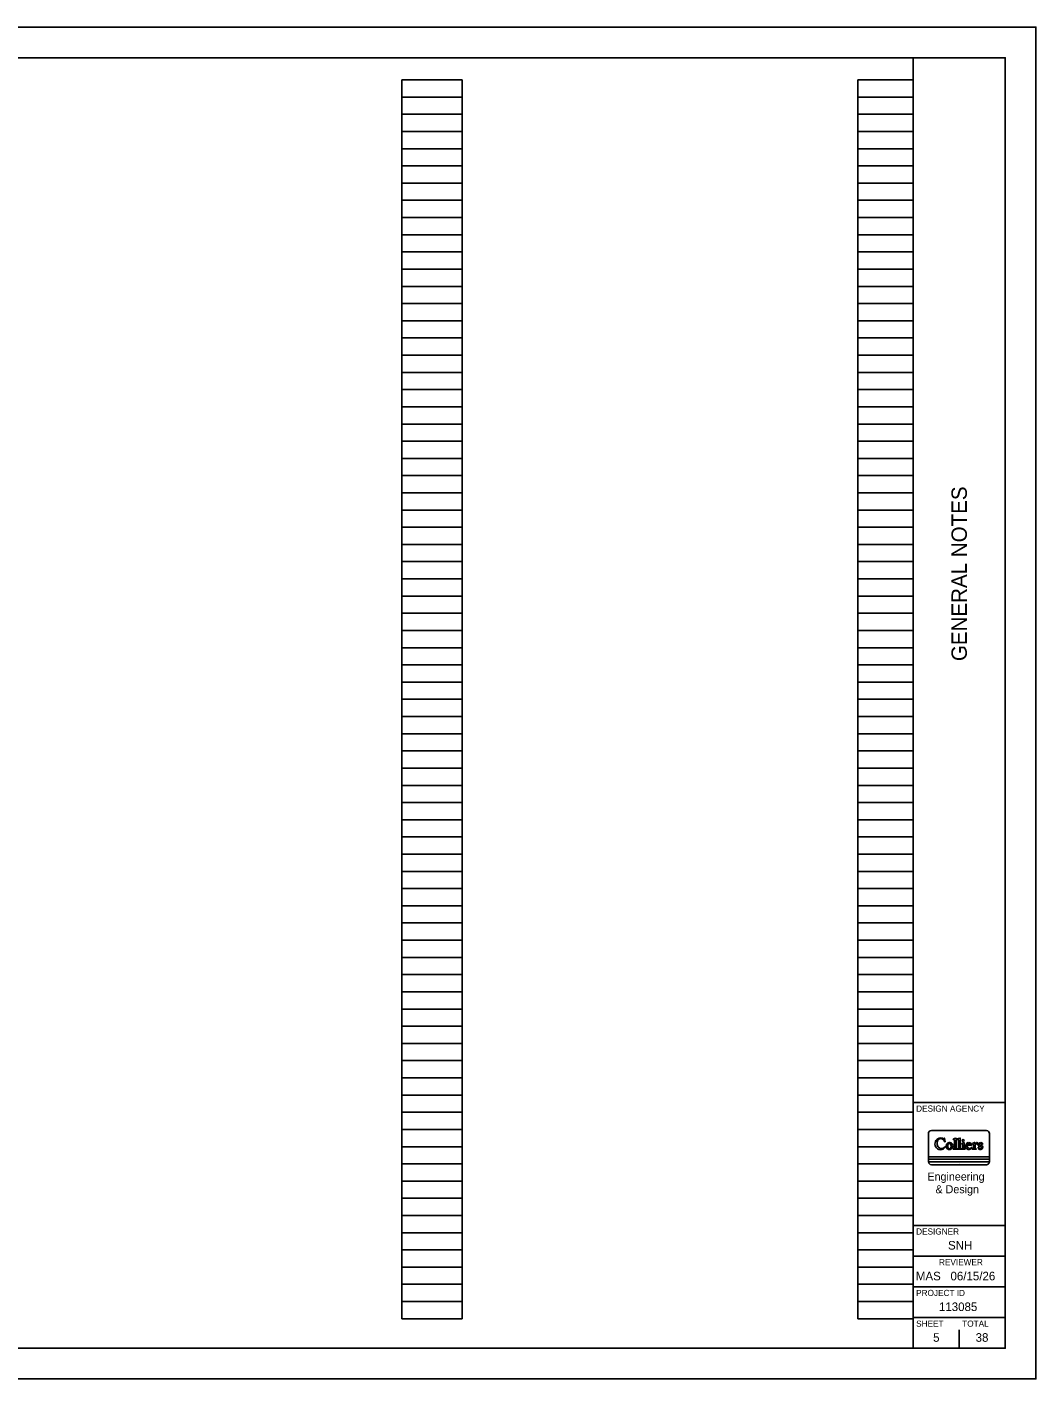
# Model space of a CAD drawing. Extents: x 0 to 34, y 0 to 22.
# Drawn here: x 17.58 to 34, y 0 to 22 of the extents above; entities that cross this region are included whole.
import ezdxf

# ---------------------------------------------------------------- set-up
doc = ezdxf.new("R2010")
doc.units = 0
for name, color, linetype in [('SH_Border', 7, 'Continuous'), ('SH_Cut_Line', 7, 'Continuous'), ('SH_Data', 7, 'Continuous')]:
    doc.layers.add(name, color=color, linetype=linetype)

msp = doc.modelspace()

# ---------------------------------------------------------------- linework, layer by layer
at = {"layer": 'SH_Border'}
for p, q in [((32, 0.5), (32, 21.5)), ((32, 4.5), (33.5, 4.5)), ((32, 2.5), (33.5, 2.5)), ((32, 2), (33.5, 2)), ((32, 1.5), (33.5, 1.5)), ((32, 1), (33.5, 1))]:
    msp.add_line(p, q, dxfattribs=at)
msp.add_lwpolyline([(1.5, 21.5), (33.5, 21.5), (33.5, 0.5), (1.5, 0.5)], close=True, dxfattribs=at)
at = {"layer": 'SH_Cut_Line'}
msp.add_lwpolyline([(0, 0), (34, 0), (34, 22), (0, 22)], close=True, dxfattribs=at)
at = {"layer": 'SH_Data'}
for p, q in [((23.68, 0.98), (23.68, 21.14)), ((23.68, 21.14), (24.66, 21.14)), ((24.66, 0.98), (24.66, 21.14)), ((31.1, 0.98), (31.1, 21.14)), ((31.1, 21.14), (32, 21.14)), ((32, 0.98), (32, 21.14)), ((23.68, 20.86), (24.66, 20.86)), ((31.1, 20.86), (32, 20.86)), ((23.68, 20.58), (24.66, 20.58)), ((31.1, 20.58), (32, 20.58)), ((23.68, 20.3), (24.66, 20.3)), ((31.1, 20.3), (32, 20.3)), ((23.68, 20.02), (24.66, 20.02)), ((31.1, 20.02), (32, 20.02)), ((23.68, 19.74), (24.66, 19.74)), ((31.1, 19.74), (32, 19.74)), ((23.68, 19.46), (24.66, 19.46)), ((31.1, 19.46), (32, 19.46)), ((23.68, 19.18), (24.66, 19.18)), ((31.1, 19.18), (32, 19.18)), ((23.68, 18.9), (24.66, 18.9)), ((31.1, 18.9), (32, 18.9)), ((23.68, 18.62), (24.66, 18.62)), ((31.1, 18.62), (32, 18.62)), ((23.68, 18.34), (24.66, 18.34)), ((31.1, 18.34), (32, 18.34)), ((23.68, 18.06), (24.66, 18.06)), ((31.1, 18.06), (32, 18.06)), ((23.68, 17.78), (24.66, 17.78)), ((31.1, 17.78), (32, 17.78)), ((23.68, 17.5), (24.66, 17.5)), ((31.1, 17.5), (32, 17.5)), ((23.68, 17.22), (24.66, 17.22)), ((31.1, 17.22), (32, 17.22)), ((23.68, 16.94), (24.66, 16.94)), ((31.1, 16.94), (32, 16.94)), ((23.68, 16.66), (24.66, 16.66)), ((31.1, 16.66), (32, 16.66)), ((23.68, 16.38), (24.66, 16.38)), ((31.1, 16.38), (32, 16.38)), ((23.68, 16.1), (24.66, 16.1)), ((31.1, 16.1), (32, 16.1)), ((23.68, 15.82), (24.66, 15.82)), ((31.1, 15.82), (32, 15.82)), ((23.68, 15.54), (24.66, 15.54)), ((31.1, 15.54), (32, 15.54)), ((23.68, 15.26), (24.66, 15.26)), ((31.1, 15.26), (32, 15.26)), ((23.68, 14.98), (24.66, 14.98)), ((31.1, 14.98), (32, 14.98)), ((23.68, 14.7), (24.66, 14.7)), ((31.1, 14.7), (32, 14.7)), ((23.68, 14.42), (24.66, 14.42)), ((31.1, 14.42), (32, 14.42)), ((23.68, 14.14), (24.66, 14.14)), ((31.1, 14.14), (32, 14.14)), ((23.68, 13.86), (24.66, 13.86)), ((31.1, 13.86), (32, 13.86)), ((23.68, 13.58), (24.66, 13.58)), ((31.1, 13.58), (32, 13.58)), ((23.68, 13.3), (24.66, 13.3)), ((31.1, 13.3), (32, 13.3)), ((23.68, 13.02), (24.66, 13.02)), ((31.1, 13.02), (32, 13.02)), ((23.68, 12.74), (24.66, 12.74)), ((31.1, 12.74), (32, 12.74)), ((23.68, 12.46), (24.66, 12.46)), ((31.1, 12.46), (32, 12.46)), ((23.68, 12.18), (24.66, 12.18)), ((31.1, 12.18), (32, 12.18)), ((23.68, 11.9), (24.66, 11.9)), ((31.1, 11.9), (32, 11.9)), ((23.68, 11.62), (24.66, 11.62)), ((31.1, 11.62), (32, 11.62)), ((23.68, 11.34), (24.66, 11.34)), ((31.1, 11.34), (32, 11.34)), ((23.68, 11.06), (24.66, 11.06)), ((31.1, 11.06), (32, 11.06)), ((23.68, 10.78), (24.66, 10.78)), ((31.1, 10.78), (32, 10.78)), ((23.68, 10.5), (24.66, 10.5)), ((31.1, 10.5), (32, 10.5)), ((23.68, 10.22), (24.66, 10.22)), ((31.1, 10.22), (32, 10.22)), ((23.68, 9.94), (24.66, 9.94)), ((31.1, 9.94), (32, 9.94)), ((23.68, 9.66), (24.66, 9.66)), ((31.1, 9.66), (32, 9.66)), ((23.68, 9.38), (24.66, 9.38)), ((31.1, 9.38), (32, 9.38)), ((23.68, 9.1), (24.66, 9.1)), ((31.1, 9.1), (32, 9.1)), ((23.68, 8.82), (24.66, 8.82)), ((31.1, 8.82), (32, 8.82)), ((23.68, 8.54), (24.66, 8.54)), ((31.1, 8.54), (32, 8.54)), ((23.68, 8.26), (24.66, 8.26)), ((31.1, 8.26), (32, 8.26)), ((23.68, 7.98), (24.66, 7.98)), ((31.1, 7.98), (32, 7.98)), ((23.68, 7.7), (24.66, 7.7)), ((31.1, 7.7), (32, 7.7)), ((23.68, 7.42), (24.66, 7.42)), ((31.1, 7.42), (32, 7.42)), ((23.68, 7.14), (24.66, 7.14)), ((31.1, 7.14), (32, 7.14)), ((23.68, 6.86), (24.66, 6.86)), ((31.1, 6.86), (32, 6.86)), ((23.68, 6.58), (24.66, 6.58)), ((31.1, 6.58), (32, 6.58)), ((23.68, 6.3), (24.66, 6.3)), ((31.1, 6.3), (32, 6.3)), ((23.68, 6.02), (24.66, 6.02)), ((31.1, 6.02), (32, 6.02)), ((23.68, 5.74), (24.66, 5.74)), ((31.1, 5.74), (32, 5.74)), ((23.68, 5.46), (24.66, 5.46)), ((31.1, 5.46), (32, 5.46)), ((23.68, 5.18), (24.66, 5.18)), ((31.1, 5.18), (32, 5.18)), ((23.68, 4.9), (24.66, 4.9)), ((31.1, 4.9), (32, 4.9)), ((23.68, 4.62), (24.66, 4.62)), ((31.1, 4.62), (32, 4.62)), ((23.68, 4.34), (24.66, 4.34)), ((31.1, 4.34), (32, 4.34)), ((23.68, 4.06), (24.66, 4.06)), ((31.1, 4.06), (32, 4.06)), ((33.195, 4.043), (32.299, 4.043)), ((23.68, 3.78), (24.66, 3.78)), ((31.1, 3.78), (32, 3.78)), ((32.506, 3.913), (32.507, 3.91)), ((32.511, 3.864), (32.513, 3.859)), ((32.518, 3.765), (32.522, 3.77)), ((32.596, 3.846), (32.59, 3.846)), ((32.667, 3.745), (32.658, 3.745)), ((32.674, 3.881), (32.674, 3.753)), ((32.701, 3.752), (32.701, 3.916)), ((32.734, 3.745), (32.707, 3.745)), ((32.741, 3.879), (32.741, 3.751)), ((32.768, 3.751), (32.768, 3.916)), ((32.799, 3.745), (32.774, 3.745)), ((32.827, 3.846), (32.791, 3.832)), ((32.805, 3.812), (32.805, 3.751)), ((32.832, 3.749), (32.832, 3.843)), ((32.845, 3.745), (32.836, 3.745)), ((32.886, 3.802), (32.947, 3.802)), ((32.919, 3.81), (32.887, 3.81)), ((32.975, 3.745), (32.968, 3.745)), ((33, 3.846), (32.969, 3.831)), ((32.969, 3.825), (32.976, 3.821)), ((32.982, 3.81), (32.982, 3.753)), ((33.007, 3.828), (33.006, 3.843)), ((33.01, 3.753), (33.01, 3.807)), ((33.026, 3.745), (33.017, 3.745)), ((33.11, 3.833), (33.125, 3.816)), ((33.132, 3.82), (33.13, 3.835)), ((32.249, 3.533), (33.244, 3.533)), ((33.244, 3.533), (32.249, 3.533)), ((32.658, 3.737), (32.845, 3.737)), ((32.968, 3.737), (33.026, 3.737)), ((33.245, 3.535), (33.245, 3.575)), ((23.68, 3.5), (24.66, 3.5)), ((31.1, 3.5), (32, 3.5)), ((32.299, 3.485), (33.195, 3.485)), ((32.75, 3.5), (32.75, 3.5)), ((23.68, 3.22), (24.66, 3.22)), ((31.1, 3.22), (32, 3.22)), ((23.68, 2.94), (24.66, 2.94)), ((31.1, 2.94), (32, 2.94)), ((23.68, 2.66), (24.66, 2.66)), ((31.1, 2.66), (32, 2.66)), ((23.68, 2.38), (24.66, 2.38)), ((31.1, 2.38), (32, 2.38)), ((23.68, 2.1), (24.66, 2.1)), ((31.1, 2.1), (32, 2.1)), ((23.68, 1.82), (24.66, 1.82)), ((31.1, 1.82), (32, 1.82)), ((23.68, 1.54), (24.66, 1.54)), ((31.1, 1.54), (32, 1.54)), ((23.68, 1.26), (24.66, 1.26)), ((31.1, 1.26), (32, 1.26)), ((23.68, 0.98), (24.66, 0.98)), ((31.1, 0.98), (32, 0.98)), ((32.375, 0.675), (32.375, 0.675)), ((32.75, 0.5), (32.75, 0.8))]:
    msp.add_line(p, q, dxfattribs=at)
for points in [[(32.249, 3.993), (32.249, 3.617), (33.245, 3.617), (33.245, 3.993)], [(32.521, 3.861), (32.516, 3.886), (32.514, 3.914)], [(33.245, 3.575), (32.249, 3.575), (32.249, 3.535)]]:
    msp.add_lwpolyline(points, dxfattribs=at)
msp.add_lwpolyline([(33.245, 3.617), (32.249, 3.617), (32.249, 3.575), (33.245, 3.575)], close=True, dxfattribs=at)
msp.add_circle((32.815, 3.879), 0.0155, dxfattribs=at)
for centre, radius, start, end in [((32.299, 3.993), 0.0498, 90, 180), ((33.195, 3.993), 0.0498, 0, 90), ((32.456, 3.826), 0.0996, 122.7772, 219.4331), ((32.445, 3.817), 0.0857, 219.4331, 285.3506), ((32.526, 3.843), 0.135, 175.9543, 206.5569), ((32.457, 3.848), 0.0652, 110.6135, 175.9543), ((32.45, 3.835), 0.0884, 54.7696, 122.7772), ((32.458, 3.81), 0.059, 206.5569, 271.2175), ((32.45, 3.867), 0.0454, 67.8997, 110.6135), ((32.458, 3.828), 0.0773, 271.2175, 317.7042), ((32.437, 3.835), 0.0794, 21.2674, 67.8997), ((32.44, 3.834), 0.104, 285.3506, 318.3029), ((32.503, 3.91), 0.00381, 234.7696, 0.2433), ((32.51, 3.914), 0.00392, 10.93, 183.8175), ((32.516, 3.862), 0.00427, 213.048, 354.7379), ((32.518, 3.773), 0.00456, 317.5815, 137.7042), ((32.594, 3.79), 0.0573, 155.0154, 195.9836), ((32.593, 3.79), 0.0568, 195.9836, 247.4134), ((32.591, 3.791), 0.0549, 91.4708, 155.0154), ((32.627, 3.79), 0.0628, 159.8672, 197.1421), ((32.617, 3.787), 0.0527, 197.1421, 229.9048), ((32.613, 3.795), 0.0485, 128.4847, 159.8672), ((32.592, 3.822), 0.0143, 51.5153, 128.4847), ((32.593, 3.759), 0.0157, 229.9048, 310.0952), ((32.596, 3.791), 0.0547, 22.5432, 90), ((32.572, 3.797), 0.0457, 8.6045, 51.5153), ((32.573, 3.782), 0.0463, 311.5123, 356.3189), ((32.586, 3.797), 0.0652, 292.5866, 340.2533), ((32.532, 3.787), 0.0872, 354.2931, 11.1311), ((32.599, 3.792), 0.0508, 340.2533, 22.5432), ((32.657, 3.901), 0.00323, 122.5943, 271.3615), ((32.658, 3.741), 0.00412, 90, 270), ((32.544, 4.221), 0.336, 289.2258, 296.5694), ((32.657, 3.881), 0.0166, 0, 91.3615), ((32.667, 3.752), 0.00695, 270, 7.6881), ((32.696, 3.916), 0.00466, 0.7043, 112.8976), ((32.709, 3.752), 0.00806, 180, 256.9766), ((32.724, 3.902), 0.00377, 108.5217, 257.147), ((32.641, 4.168), 0.275, 287.2899, 295.7863), ((32.722, 3.879), 0.019, 0, 85.065), ((32.734, 3.751), 0.0065, 270, 3.1556), ((32.763, 3.916), 0.00504, 3.9002, 114.2106), ((32.775, 3.751), 0.00652, 179.2506, 264.6402), ((32.794, 3.829), 0.00399, 126.9098, 263.7558), ((32.792, 3.812), 0.0128, 0, 83.7558), ((32.799, 3.75), 0.00532, 270, 12.3402), ((32.829, 3.843), 0.00324, 356.2318, 111.3032), ((32.837, 3.749), 0.00485, 180, 266.7746), ((32.845, 3.741), 0.00381, 270, 90), ((32.936, 3.789), 0.0786, 158.9201, 196.7689), ((32.904, 3.78), 0.0455, 196.7689, 259.4625), ((32.906, 3.801), 0.0468, 107.3884, 158.9201), ((32.928, 3.794), 0.0459, 174.8749, 230.9242), ((32.886, 3.798), 0.00367, 90, 174.8749), ((32.917, 3.807), 0.0332, 120.4846, 167.2691), ((32.887, 3.813), 0.00338, 167.2691, 270), ((32.909, 3.792), 0.0557, 72.6116, 107.3884), ((32.906, 3.79), 0.0563, 259.4625, 329.9587), ((32.92, 3.784), 0.0321, 230.9242, 328.1623), ((32.907, 3.823), 0.0144, 42.3189, 120.4846), ((32.901, 3.817), 0.0231, 354.1231, 42.3189), ((32.918, 3.815), 0.00543, 277.2594, 354.1231), ((32.914, 3.809), 0.0381, 357.2625, 72.6116), ((32.946, 3.807), 0.00555, 272.7564, 357.2625), ((32.951, 3.764), 0.00454, 329.9587, 148.1623), ((32.968, 3.741), 0.00381, 91.0116, 270), ((32.971, 3.828), 0.0034, 121.2415, 241.2505), ((32.975, 3.752), 0.00704, 270, 9.7141), ((32.969, 3.81), 0.0136, 0, 59.7444), ((33.002, 3.843), 0.00375, 6.4513, 116.174), ((33.009, 3.828), 0.00158, 185.3907, 323.4477), ((33.094, 3.765), 0.104, 130.2856, 143.4477), ((33.033, 3.807), 0.0235, 141.4263, 180.0327), ((33.018, 3.752), 0.00796, 179.3196, 263.9925), ((33.023, 3.815), 0.0105, 58.8554, 141.4263), ((33.038, 3.831), 0.0179, 49.7144, 130.2856), ((33.026, 3.741), 0.00381, 270, 90), ((33.038, 3.839), 0.018, 238.8554, 310.2856), ((33.041, 3.835), 0.0124, 310.2856, 49.7144), ((33.093, 3.812), 0.0332, 143.4089, 199.3264), ((33.065, 3.768), 0.00485, 20.4198, 193.2731), ((32.948, 3.74), 0.116, 4.8826, 13.2731), ((33.087, 3.81), 0.0263, 199.3264, 242.7351), ((33.077, 3.751), 0.014, 184.8826, 242.2064), ((33.093, 3.812), 0.0334, 105.6066, 143.4089), ((33.118, 3.787), 0.0516, 200.4198, 231.7135), ((33.093, 3.782), 0.0486, 242.2064, 319.0024), ((33.141, 3.915), 0.144, 242.7351, 255.1442), ((33.093, 3.822), 0.0133, 123.6114, 236.3886), ((33.099, 3.79), 0.0558, 61.5074, 105.6066), ((33.099, 3.813), 0.0238, 78.1441, 123.6114), ((33.111, 3.85), 0.0468, 236.3886, 262.0524), ((33.098, 3.761), 0.0185, 231.7135, 325.4966), ((33.101, 3.825), 0.0115, 42.5173, 78.1441), ((33.1, 3.76), 0.016, 325.4966, 75.1442), ((33.099, 3.763), 0.0407, 40.9976, 82.0524), ((33.128, 3.819), 0.00433, 219.7222, 9.1323), ((33.122, 3.833), 0.00795, 16.8946, 61.5074), ((33.107, 3.77), 0.0305, 319.0024, 40.9976), ((32.299, 3.535), 0.0498, 180, 183.1495), ((32.299, 3.535), 0.0498, 183.1495, 270), ((32.591, 3.784), 0.0512, 247.4134, 292.5866), ((33.195, 3.535), 0.0498, 270, 356.8505), ((33.195, 3.535), 0.0498, 356.8505, 0)]:
    msp.add_arc(centre, radius, start, end, dxfattribs=at)

# ---------------------------------------------------------------- texts
msp.add_text('GENERAL NOTES', height=0.25, rotation=90, dxfattribs=at).set_placement((32.875, 11.682))
for s, height, p in [('DESIGN AGENCY', 0.1, (32.05, 4.35)), ('Engineering', 0.13025, (32.234, 3.229)), ('& Design', 0.1303, (32.365, 3.022)), ('DESIGNER', 0.1, (32.05, 2.35)), ('SNH', 0.14, (32.569, 2.105)), ('REVIEWER', 0.1, (32.422, 1.85)), ('MAS', 0.14, (32.045, 1.605)), ('06/15/26', 0.14, (32.609, 1.605)), ('PROJECT ID', 0.1, (32.05, 1.35)), ('113085', 0.14, (32.421, 1.105)), ('SHEET', 0.1, (32.05, 0.85)), ('TOTAL', 0.1, (32.8, 0.85)), ('5', 0.14, (32.326, 0.605)), ('38', 0.14, (33.018, 0.605))]:
    msp.add_text(s, height=height, dxfattribs=at).set_placement(p)

doc.saveas('drawing.dxf')
